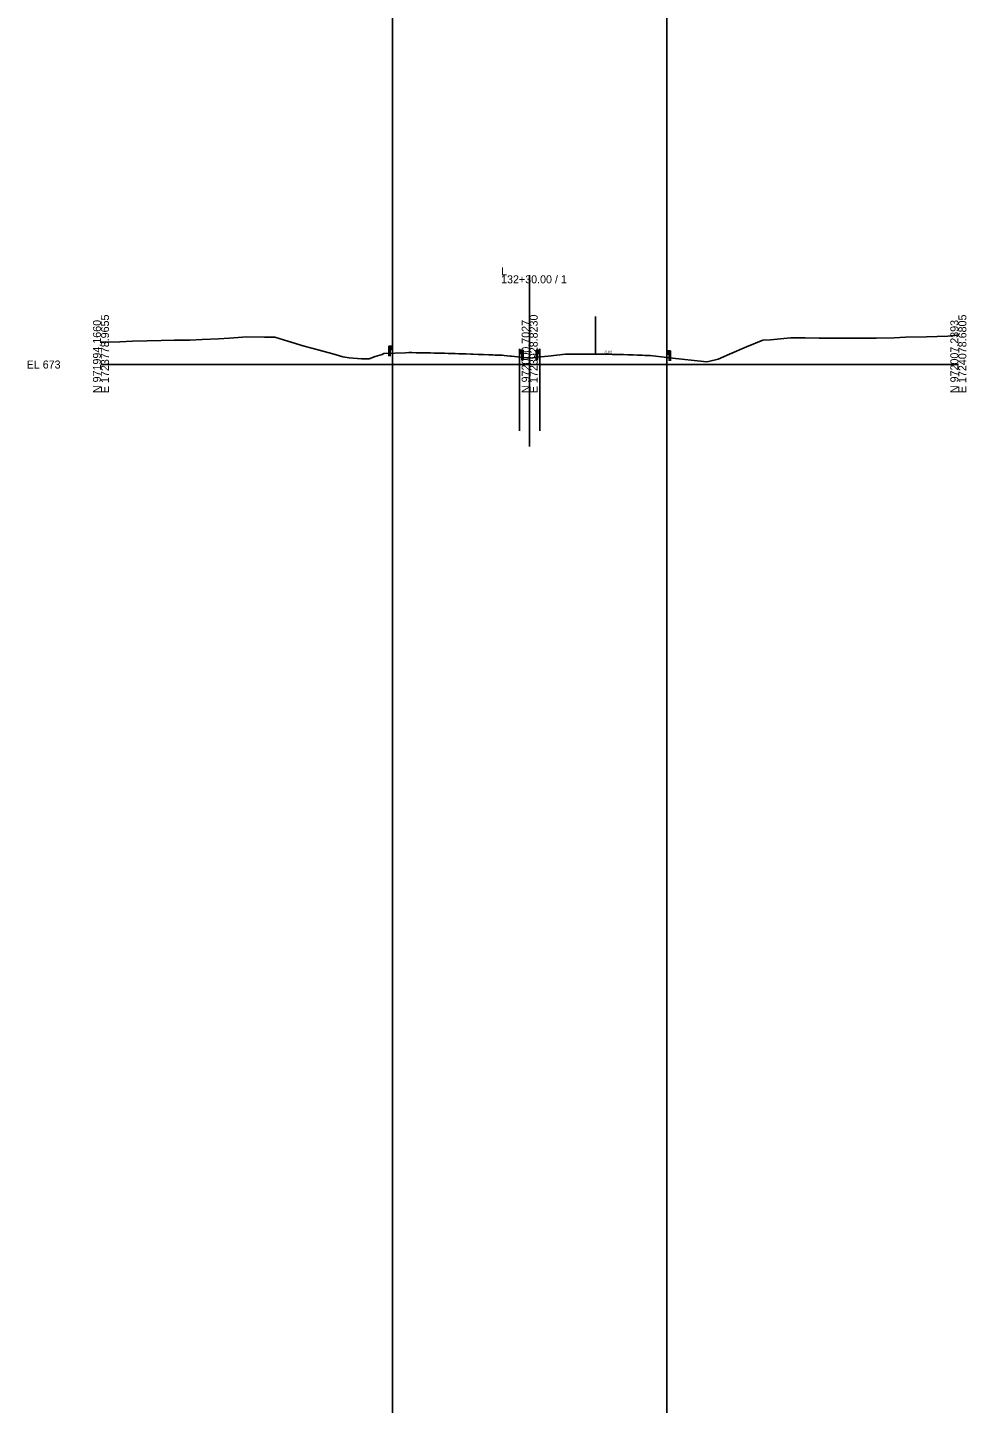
# Model space of a CAD drawing. Extents: x -26 to 303, y -29 to 15026.
# Drawn here: x -25.7 to 302.8, y 12136.4 to 12617.9 of the extents above; entities that cross this region are included whole.
import ezdxf

# ---------------------------------------------------------------- set-up
doc = ezdxf.new("R2010")
doc.units = 0
for name, color, linetype in [('Exist Cross Section Cell', 7, 'Continuous'), ('Exist XS Center Line Elevation Label', 7, 'Continuous'), ('Exist XS Ground Line', 7, 'Continuous'), ('Prop XS Ditch Standard Text', 7, 'Continuous'), ('Scratch_Level_0', 7, 'Continuous'), ('Typical Guardrail CELL', 7, 'Continuous')]:
    doc.layers.add(name, color=color, linetype=linetype)

msp = doc.modelspace()

# ---------------------------------------------------------------- linework, layer by layer
at = {"layer": 'Exist Cross Section Cell'}
for p, q in [((150, 12500), (150, 12531.22)), ((0, 12500), (150, 12500)), ((150, 12500), (300, 12500))]:
    msp.add_line(p, q, dxfattribs=at)
at = {"layer": 'Exist XS Ground Line'}
msp.add_lwpolyline([(0, 12507.85), (1.05, 12507.86), (6.6, 12507.97), (11.06, 12508.15), (16.19, 12508.26), (21.07, 12508.37), (25.78, 12508.51), (31.08, 12508.54), (35.37, 12508.71), (41.08, 12508.95), (44.96, 12509.21), (51.09, 12509.65), (57.23, 12509.55), (60.84, 12509.52), (65.44, 12508.17), (71.11, 12506.45), (73.73, 12505.69), (81.12, 12503.71), (84.63, 12502.75), (86.87, 12502.31), (91.22, 12502.01), (92.19, 12501.98), (93.87, 12502.03), (95.97, 12502.8), (98.34, 12503.49), (99, 12503.9), (106.58, 12504.15), (107.69, 12504.18), (108.14, 12504.18), (108.79, 12504.17), (110.24, 12504.15), (111.38, 12504.15), (112.76, 12504.1), (114.26, 12504.07), (115.26, 12504.04), (116.64, 12504.02), (117.76, 12504), (119.04, 12503.96), (120.25, 12503.92), (121.44, 12503.89), (123.11, 12503.86), (123.89, 12503.84), (125.24, 12503.8), (126.78, 12503.75), (127.73, 12503.72), (129.4, 12503.67), (130.24, 12503.64), (132.04, 12503.56), (132.75, 12503.53), (133.86, 12503.49), (135.66, 12503.41), (137.17, 12503.36), (137.76, 12503.33), (139.86, 12503.25), (140.41, 12503.23), (141.03, 12503.2), (142.17, 12503.08), (143.15, 12502.98), (143.7, 12502.92), (150.01, 12502.27), (153.91, 12502.69), (156.42, 12502.94), (162.52, 12503.62), (163.63, 12503.64), (164.24, 12503.65), (164.72, 12503.65), (165.3, 12503.65), (167, 12503.65), (167.79, 12503.65), (169.39, 12503.66), (170.31, 12503.66), (171.81, 12503.66), (172.81, 12503.65), (174.19, 12503.65), (175.31, 12503.65), (176.3, 12503.63), (177.07, 12503.62), (177.8, 12503.6), (178.97, 12503.56), (180.29, 12503.51), (181.74, 12503.48), (182.78, 12503.46), (184.35, 12503.41), (185.29, 12503.38), (186.16, 12503.35), (187.79, 12503.31), (188.84, 12503.27), (189.32, 12503.26), (190.3, 12503.2), (190.88, 12503.18), (192.17, 12503.14), (197.11, 12502.57), (199.99, 12502.24), (210.81, 12501.05), (211.97, 12500.92), (212.6, 12501.1), (215.99, 12501.89), (219.9, 12503.66), (225.91, 12506.14), (231.59, 12508.52), (234.28, 12508.67), (241.26, 12509.36), (246.36, 12509.34), (251.27, 12509.23), (255.95, 12509.27), (261.28, 12509.28), (265.54, 12509.28), (271.29, 12509.17), (277.56, 12509.29), (281.46, 12509.52), (288.89, 12509.64), (296.36, 12509.97), (297.35, 12510.02), (298.08, 12510.06), (300, 12510.41)], dxfattribs=at)
at = {"layer": 'Scratch_Level_0'}
for p, q in [((102, 15009.56), (102, -28.7)), ((198, 15009.56), (198, -28.7)), ((173, 12516.8), (173, 12503.65)), ((146.46, 12505.5), (146.46, 12476.8)), ((153.54, 12505.5), (153.54, 12476.8)), ((173, 12503.65), (181.74, 12503.48)), ((150, 12500), (150, 12471.3))]:
    msp.add_line(p, q, dxfattribs=at)
at = {"layer": 'Typical Guardrail CELL'}
for p, q in [((101.18, 12506.44), (100.68, 12506.44)), ((100.68, 12506.44), (100.68, 12503.95)), ((101.18, 12506.44), (101.18, 12503.95)), ((101.18, 12506.44), (101.68, 12506.44)), ((101.68, 12506.44), (101.68, 12505.28)), ((101.68, 12506.44), (101.97, 12506.23)), ((101.18, 12503.95), (100.68, 12503.95)), ((100.68, 12503.95), (100.68, 12502.94)), ((101.18, 12505.28), (101.68, 12505.28)), ((101.18, 12503.95), (101.18, 12502.94)), ((101.68, 12505.9), (101.97, 12506.11)), ((101.68, 12505.86), (101.68, 12505.9)), ((101.68, 12505.86), (101.68, 12505.81)), ((101.68, 12505.81), (101.97, 12505.61)), ((101.68, 12505.28), (101.97, 12505.48)), ((146.78, 12504.98), (146.49, 12504.78)), ((146.78, 12504.45), (146.49, 12504.65)), ((146.78, 12504.36), (146.49, 12504.15)), ((146.78, 12503.82), (146.49, 12504.03)), ((147.28, 12504.98), (146.78, 12504.98)), ((146.78, 12504.98), (146.78, 12503.82)), ((146.78, 12504.4), (146.78, 12504.45)), ((146.78, 12504.4), (146.78, 12504.36)), ((147.28, 12503.82), (146.78, 12503.82)), ((147.28, 12504.98), (147.28, 12502.5)), ((147.28, 12504.98), (147.78, 12504.98)), ((147.28, 12502.5), (147.78, 12502.5)), ((147.28, 12502.5), (147.28, 12501.49)), ((147.78, 12504.98), (147.78, 12502.5)), ((147.78, 12502.5), (147.78, 12501.49)), ((152.72, 12504.99), (152.22, 12504.99)), ((152.22, 12504.99), (152.22, 12502.51)), ((152.72, 12502.51), (152.22, 12502.51)), ((152.22, 12502.51), (152.22, 12501.5)), ((152.72, 12504.99), (152.72, 12502.51)), ((152.72, 12504.99), (153.22, 12504.99)), ((152.72, 12503.83), (153.22, 12503.83)), ((152.72, 12502.51), (152.72, 12501.5)), ((153.22, 12504.99), (153.22, 12503.83)), ((153.22, 12504.99), (153.51, 12504.79)), ((153.22, 12504.46), (153.51, 12504.66)), ((153.22, 12504.41), (153.22, 12504.46)), ((153.22, 12504.41), (153.22, 12504.37)), ((153.22, 12504.37), (153.51, 12504.16)), ((153.22, 12503.83), (153.51, 12504.04)), ((198.32, 12504.8), (198.03, 12504.6)), ((198.32, 12504.27), (198.03, 12504.47)), ((198.32, 12504.18), (198.03, 12503.97)), ((198.32, 12503.64), (198.03, 12503.85)), ((198.82, 12504.8), (198.32, 12504.8)), ((198.32, 12504.8), (198.32, 12503.64)), ((198.32, 12504.22), (198.32, 12504.27)), ((198.32, 12504.22), (198.32, 12504.18)), ((198.82, 12503.64), (198.32, 12503.64)), ((198.82, 12504.8), (198.82, 12502.32)), ((198.82, 12504.8), (199.32, 12504.8)), ((198.82, 12502.32), (199.32, 12502.32)), ((198.82, 12502.32), (198.82, 12501.31)), ((199.32, 12504.8), (199.32, 12502.32)), ((199.32, 12502.32), (199.32, 12501.31))]:
    msp.add_line(p, q, dxfattribs=at)
for centre, start, end in [((101.92, 12506.17), 304.9888, 54.997), ((101.92, 12505.54), 304.9634, 54.9941), ((146.54, 12504.72), 125.003, 235.0112), ((146.54, 12504.09), 125.0059, 235.0366), ((153.46, 12504.73), 304.9888, 54.997), ((153.46, 12504.1), 304.9634, 54.9941), ((198.08, 12504.54), 125.003, 235.0112), ((198.08, 12503.91), 125.0059, 235.0366)]:
    msp.add_arc(centre, 0.0776, start, end, dxfattribs=at)

# ---------------------------------------------------------------- texts
at = {"layer": 'Exist Cross Section Cell'}
for s, p in [('132+30.00 / 1', (140, 12528.42)), ('L', (140, 12531.22)), ('EL 673', (-26, 12498.6))]:
    msp.add_text(s, height=2.8, dxfattribs=at).set_placement(p)
for s, p in [('E 1723778.9655', (2.8, 12490)), ('E 1723928.8230', (152.8, 12490)), ('E 1724078.6805', (302.8, 12490)), ('N 971994.1660', (0, 12490)), ('N 972000.7027', (150, 12490)), ('N 972007.2393', (300, 12490))]:
    msp.add_text(s, height=2.8, rotation=90, dxfattribs=at).set_placement(p)
at = {"layer": 'Exist XS Center Line Elevation Label'}
msp.add_text('675.27', height=0.18, dxfattribs=at).set_placement((149.61, 12501.78))
at = {"layer": 'Prop XS Ditch Standard Text'}
msp.add_text('0.02', height=1, rotation=358.8973, dxfattribs=at).set_placement((176.22, 12503.84))

doc.saveas('drawing.dxf')
